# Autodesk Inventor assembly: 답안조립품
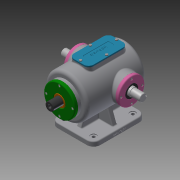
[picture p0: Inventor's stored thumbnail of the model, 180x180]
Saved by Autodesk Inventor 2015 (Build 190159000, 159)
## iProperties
Created: 2021-11
Part Number: 답안조립품
Document SubType Name: Assembly
Designer: G08
Author: G08
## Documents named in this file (14)
- C:\Users\G08\Desktop\711106V1036\답안조립품.iam
- C:\Users\G08\Desktop\711106V1036\베어링 6205.ipt
- 베어링 6205.ipt
- C:\Users\G08\Desktop\711106V1036\본체.ipt
- C:\Users\G08\Desktop\711106V1036\볼트 M4x0.7.ipt
- C:\Users\G08\Desktop\711106V1036\부시.ipt
- C:\Users\G08\Desktop\711106V1036\상부커버.ipt
- C:\Users\G08\Desktop\711106V1036\슬라이드 커버.ipt
- C:\Users\G08\Desktop\711106V1036\슬라이드.ipt
- C:\Users\G08\Desktop\711106V1036\오일실.ipt
- 오일실.ipt
- C:\Users\G08\Desktop\711106V1036\육각머리볼트 M4.ipt
- C:\Users\G08\Desktop\711106V1036\축 커버.ipt
- C:\Users\G08\Desktop\711106V1036\편심축.ipt
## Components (12 placed, 1 different names)
1. M4x0.7:2
2. M4x0.7:3
3. M4x0.7:4
4. M4x0.7:5
5. M4x0.7:6
6. M4x0.7:7
7. M4x0.7:8
8. M4x0.7:9
9. M4x0.7:1
10. M4x0.7:10
11. M4x0.7:11
12. M4x0.7:12
